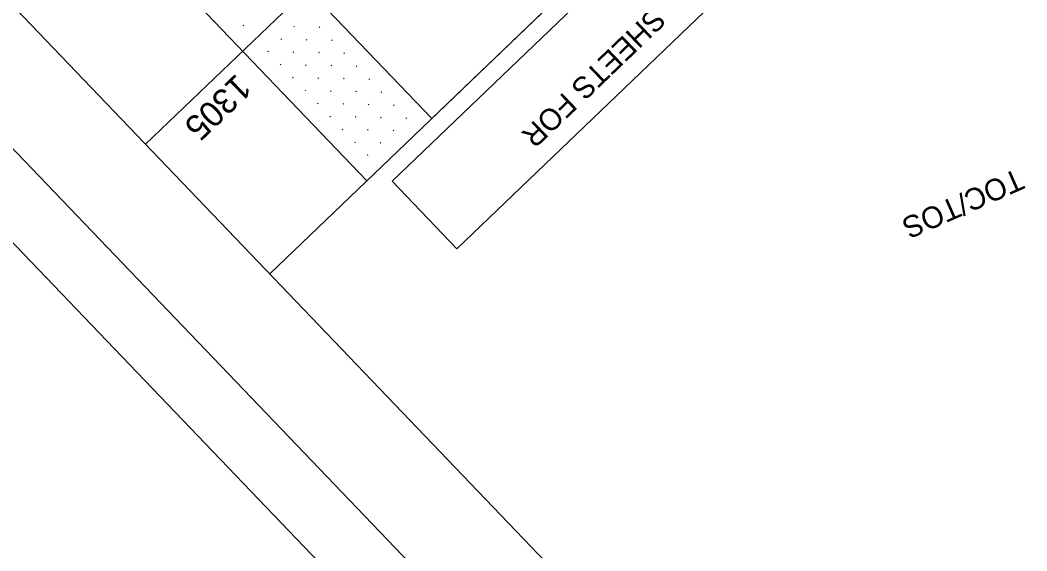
# Model space of a CAD drawing. Extents: x 2148987 to 2151117, y 142806 to 144993.
# Drawn here: x 2149366.7 to 2149647, y 143192.6 to 143340.3 of the extents above; entities that cross this region are included whole.
import ezdxf

# ---------------------------------------------------------------- set-up
doc = ezdxf.new("R2010")
doc.units = 0
for name, color, linetype in [('BASELINE', 7, 'Continuous'), ('PR_ABUT_PH3', 7, 'Continuous'), ('PR_Grading_Txt', 7, 'Continuous'), ('PR_PIER_PH3', 7, 'Continuous'), ('PR_Road_Asphalt', 7, 'Continuous'), ('PR_Road_Concrete', 7, 'Continuous'), ('PR_Storm_Txt', 7, 'Continuous'), ('SHT_Profile_Grid_Minor', 7, 'Continuous'), ('Wall D Bore', 7, 'Continuous')]:
    doc.layers.add(name, color=color, linetype=linetype)

msp = doc.modelspace()

# ---------------------------------------------------------------- linework, layer by layer
at = {"layer": 'BASELINE'}
msp.add_lwpolyline([(2151029.45, 144024.32), (2149802.07, 142848.08), (2149040.98, 143642.27), (2150268.36, 144818.51)], close=True, dxfattribs=at)
at = {"layer": 'PR_ABUT_PH3'}
msp.add_lwpolyline([(2151117.11, 144051.19), (2149817.52, 142805.76), (2148987.24, 143672.15), (2150286.82, 144917.58)], close=True, dxfattribs=at)
at = {"layer": 'PR_PIER_PH3'}
msp.add_line((2150538.73, 144395.47), (2149401.59, 143305.72), dxfattribs=at)
at = {"layer": 'PR_Road_Asphalt'}
msp.add_lwpolyline([(2149643.76, 143468.54), (2149481.31, 143312.87), (2149450.18, 143345.35), (2149612.63, 143501.03)], close=True, dxfattribs=at)
at = {"layer": 'PR_Road_Concrete'}
for p, q in [((2150573.32, 144359.37), (2149436.19, 143269.62)), ((2149134.61, 143638.51), (2149463.26, 143295.57))]:
    msp.add_line(p, q, dxfattribs=at)
msp.add_lwpolyline([(2150941.76, 143974.91), (2149804.63, 142885.16), (2149078.13, 143643.25), (2150215.26, 144733)], close=True, dxfattribs=at)
at = {"layer": 'PR_Storm_Txt'}
msp.add_lwpolyline([(2149630.72, 143413.08), (2149488.34, 143276.63), (2149470.33, 143295.42), (2149612.72, 143431.87)], close=True, dxfattribs=at)
at = {"layer": 'SHT_Profile_Grid_Minor'}
for p, q in [((2149428.91, 143338.82), (2149428.73, 143338.65)), ((2149443.05, 143338.52), (2149442.87, 143338.35)), ((2149450.12, 143338.37), (2149449.94, 143338.2)), ((2149439.44, 143335.06), (2149439.26, 143334.89)), ((2149446.51, 143334.91), (2149446.33, 143334.74)), ((2149453.58, 143334.76), (2149453.4, 143334.59)), ((2149435.83, 143331.6), (2149435.65, 143331.43)), ((2149442.9, 143331.45), (2149442.72, 143331.28)), ((2149449.97, 143331.3), (2149449.79, 143331.13)), ((2149457.04, 143331.15), (2149456.86, 143330.98)), ((2149439.29, 143327.99), (2149439.11, 143327.82)), ((2149446.36, 143327.84), (2149446.18, 143327.67)), ((2149453.43, 143327.69), (2149453.25, 143327.52)), ((2149460.5, 143327.54), (2149460.32, 143327.37)), ((2149442.75, 143324.38), (2149442.57, 143324.21)), ((2149449.82, 143324.23), (2149449.64, 143324.06)), ((2149456.89, 143324.08), (2149456.71, 143323.91)), ((2149463.96, 143323.93), (2149463.77, 143323.76)), ((2149446.21, 143320.77), (2149446.03, 143320.6)), ((2149453.28, 143320.62), (2149453.1, 143320.45)), ((2149460.35, 143320.47), (2149460.16, 143320.3)), ((2149467.41, 143320.32), (2149467.23, 143320.15)), ((2149449.67, 143317.16), (2149449.49, 143316.99)), ((2149456.74, 143317.01), (2149456.55, 143316.84)), ((2149463.8, 143316.86), (2149463.62, 143316.69)), ((2149470.87, 143316.71), (2149470.69, 143316.54)), ((2149453.13, 143313.55), (2149452.94, 143313.38)), ((2149460.19, 143313.4), (2149460.01, 143313.23)), ((2149467.26, 143313.25), (2149467.08, 143313.08)), ((2149474.33, 143313.1), (2149474.15, 143312.93)), ((2149456.58, 143309.94), (2149456.4, 143309.77)), ((2149463.65, 143309.79), (2149463.47, 143309.62)), ((2149470.72, 143309.64), (2149470.54, 143309.47)), ((2149460.04, 143306.33), (2149459.86, 143306.16)), ((2149467.11, 143306.18), (2149466.93, 143306.01)), ((2149463.5, 143302.72), (2149463.32, 143302.55))]:
    msp.add_line(p, q, dxfattribs=at)

# ---------------------------------------------------------------- texts
at = {"layer": 'PR_Grading_Txt'}
msp.add_text('TOC/TOS', height=6, rotation=203.7756, dxfattribs=at).set_placement((2149644.41, 143299.11))
at = {"layer": 'PR_Storm_Txt'}
msp.add_text('SEE DRAINAGE AREA MAP SHEETS FOR', height=6, rotation=223.7809, dxfattribs=at).set_placement((2149619.5, 143417.56))
at = {"layer": 'Wall D Bore'}
msp.add_text('1305', height=7, rotation=223.7809, dxfattribs=at).set_placement((2149426.96, 143325.66))

doc.saveas('drawing.dxf')
